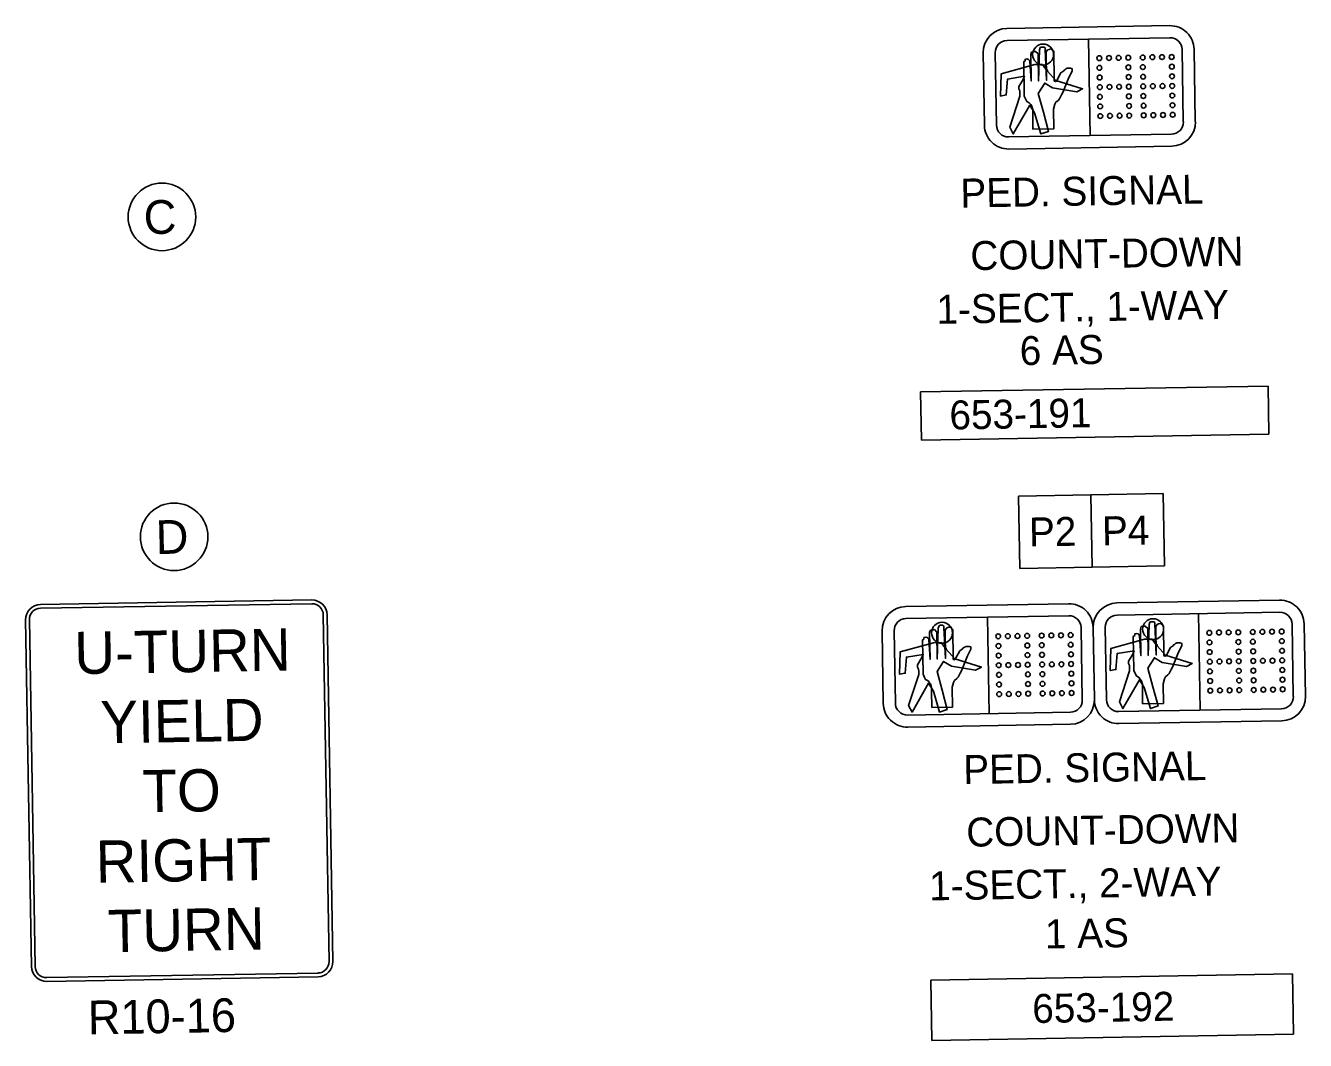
# Model space of a CAD drawing. Extents: x 924596 to 926137, y 853397 to 853834.
# Drawn here: x 925490.7 to 925596.8, y 853608.4 to 853692.5 of the extents above; entities that cross this region are included whole.
import ezdxf

# ---------------------------------------------------------------- set-up
doc = ezdxf.new("R2010")
doc.units = 0
for name, color, linetype in [('NorthArw_dp', 7, 'Continuous'), ('OverheadSign', 7, 'Continuous'), ('SignPanel', 7, 'Continuous'), ('TextNotes', 7, 'Continuous'), ('TextTables', 7, 'Continuous')]:
    doc.layers.add(name, color=color, linetype=linetype)

msp = doc.modelspace()

# ---------------------------------------------------------------- linework, layer by layer
at = {"layer": 'NorthArw_dp'}
for p, q in [((925578.79, 853691.38), (925578.92, 853683.38)), ((925564.88, 853662.12), (925593.68, 853662.61)), ((925564.95, 853658.12), (925564.88, 853662.12)), ((925593.68, 853662.61), (925593.75, 853658.61)), ((925593.75, 853658.61), (925564.95, 853658.12)), ((925572.99, 853653.48), (925578.99, 853653.59)), ((925573.09, 853647.49), (925572.99, 853653.48)), ((925578.99, 853653.59), (925584.99, 853653.69)), ((925578.99, 853653.59), (925579.09, 853647.59)), ((925579.09, 853647.59), (925578.99, 853653.59)), ((925584.99, 853653.69), (925585.09, 853647.69)), ((925579.09, 853647.59), (925573.09, 853647.49)), ((925585.09, 853647.69), (925579.09, 853647.59)), ((925587.91, 853643.74), (925588.04, 853635.74)), ((925570.41, 853643.44), (925570.55, 853635.44))]:
    msp.add_line(p, q, dxfattribs=at)
for points in [[(925572.02, 853692.26), (925585.52, 853692.49)], [(925585.54, 853691.49), (925572.04, 853691.26)], [(925570.06, 853690.23), (925570.16, 853684.23)], [(925571.06, 853690.25), (925571.16, 853684.25)], [(925586.65, 853684.51), (925586.55, 853690.51)], [(925587.65, 853684.53), (925587.55, 853690.53)], [(925572.17, 853683.26), (925585.67, 853683.49)], [(925572.19, 853682.26), (925585.69, 853682.49)], [(925581.14, 853644.62), (925594.64, 853644.85)], [(925563.64, 853644.33), (925577.14, 853644.56)], [(925577.16, 853643.56), (925563.66, 853643.33)], [(925594.66, 853643.85), (925581.16, 853643.62)], [(925578.28, 853636.57), (925578.18, 853642.57)], [(925579.18, 853642.59), (925579.28, 853636.59)], [(925580.18, 853642.61), (925580.28, 853636.61)], [(925595.77, 853636.87), (925595.67, 853642.87)], [(925596.77, 853636.89), (925596.67, 853642.89)], [(925561.68, 853642.29), (925561.78, 853636.29)], [(925562.68, 853642.31), (925562.78, 853636.31)], [(925563.8, 853635.33), (925577.29, 853635.56)], [(925581.29, 853635.62), (925594.79, 853635.85)], [(925563.81, 853634.33), (925577.31, 853634.56)], [(925581.31, 853634.62), (925594.81, 853634.85)]]:
    msp.add_lwpolyline(points, dxfattribs=at)
for points in [[(925574.19, 853683.9), (925574.17, 853685.26), (925574.17, 853685.54), (925574.08, 853685.86), (925574, 853685.94), (925573.88, 853686.09), (925573.67, 853686.21), (925573.59, 853686.37), (925573.47, 853686.65), (925573.47, 853686.73), (925573.42, 853689.49), (925573.54, 853689.57), (925573.54, 853689.69), (925573.69, 853689.73), (925573.81, 853689.69), (925573.94, 853689.57), (925573.94, 853689.53), (925574.05, 853687.9), (925574.01, 853690.1), (925574.08, 853690.3), (925574.32, 853690.34), (925574.4, 853690.34), (925574.61, 853690.15), (925574.65, 853687.91), (925574.72, 853690.47), (925574.8, 853690.67), (925574.88, 853690.71), (925575.12, 853690.71), (925575.2, 853690.64), (925575.2, 853690.52), (925575.32, 853687.96), (925575.28, 853690.32), (925575.4, 853690.48), (925575.52, 853690.52), (925575.68, 853690.56), (925575.8, 853690.49), (925575.92, 853690.37), (925575.96, 853687.97), (925575.97, 853687.89), (925576.05, 853687.85), (925576.13, 853687.89), (925576.13, 853687.89), (925576.51, 853688.58), (925576.75, 853688.74), (925576.75, 853688.78), (925576.83, 853688.82), (925576.91, 853688.91), (925577.03, 853688.95), (925577.31, 853688.95), (925577.43, 853688.91), (925577.43, 853688.83), (925577.43, 853688.79), (925577.43, 853688.75), (925577.43, 853688.71), (925577.16, 853688.19), (925576.66, 853686.94), (925576.55, 853686.74), (925576.39, 853686.42), (925576.27, 853686.29), (925576.08, 853686.13), (925576, 853685.97), (925575.89, 853685.57), (925575.91, 853683.93)], [(925574.98, 853689.27), (925574.34, 853689.26), (925571.56, 853688.49), (925571.51, 853686.65), (925571.98, 853686.74), (925572.08, 853688.06), (925573.48, 853688.29), (925573.4, 853688.09), (925573.29, 853687.88), (925573.01, 853687.44), (925573.02, 853687.24), (925573.1, 853687.08), (925573.1, 853686.88), (925573.11, 853686.68), (925573.11, 853686.64), (925572.27, 853684.07), (925572.56, 853683.51), (925573.92, 853685.89), (925574.33, 853685.26), (925574.84, 853683.51), (925575.48, 853683.72), (925575.05, 853685.31), (925574.62, 853686.87), (925575.17, 853687.72), (925575.82, 853687.33), (925577.82, 853687), (925578.3, 853687.25), (925576.09, 853687.93), (925575.39, 853688.72), (925575.39, 853688.8), (925575.27, 853688.88), (925575.27, 853688.88)], [(925565.81, 853635.96), (925565.78, 853637.32), (925565.78, 853637.6), (925565.69, 853637.92), (925565.61, 853638), (925565.49, 853638.16), (925565.29, 853638.27), (925565.2, 853638.43), (925565.08, 853638.71), (925565.08, 853638.79), (925565.03, 853641.55), (925565.15, 853641.63), (925565.15, 853641.75), (925565.31, 853641.79), (925565.43, 853641.76), (925565.55, 853641.64), (925565.55, 853641.6), (925565.66, 853639.96), (925565.62, 853642.16), (925565.7, 853642.36), (925565.94, 853642.4), (925566.02, 853642.41), (925566.22, 853642.21), (925566.26, 853639.97), (925566.33, 853642.53), (925566.41, 853642.73), (925566.49, 853642.77), (925566.73, 853642.78), (925566.81, 853642.7), (925566.81, 853642.58), (925566.94, 853640.02), (925566.9, 853642.38), (925567.01, 853642.54), (925567.13, 853642.58), (925567.29, 853642.63), (925567.41, 853642.55), (925567.54, 853642.43), (925567.58, 853640.03), (925567.58, 853639.95), (925567.66, 853639.91), (925567.74, 853639.95), (925567.74, 853639.95), (925568.13, 853640.64), (925568.36, 853640.81), (925568.36, 853640.85), (925568.44, 853640.89), (925568.52, 853640.97), (925568.64, 853641.01), (925568.92, 853641.01), (925569.04, 853640.98), (925569.04, 853640.9), (925569.04, 853640.86), (925569.04, 853640.82), (925569.04, 853640.78), (925568.77, 853640.25), (925568.27, 853639), (925568.16, 853638.8), (925568, 853638.48), (925567.89, 853638.36), (925567.69, 853638.19), (925567.61, 853638.03), (925567.5, 853637.63), (925567.53, 853635.99)], [(925583.28, 853636.26), (925583.26, 853637.62), (925583.26, 853637.9), (925583.17, 853638.22), (925583.09, 853638.3), (925582.97, 853638.45), (925582.76, 853638.57), (925582.68, 853638.73), (925582.56, 853639.01), (925582.56, 853639.09), (925582.51, 853641.85), (925582.63, 853641.93), (925582.63, 853642.05), (925582.78, 853642.09), (925582.91, 853642.05), (925583.03, 853641.93), (925583.03, 853641.89), (925583.14, 853640.26), (925583.1, 853642.46), (925583.17, 853642.66), (925583.41, 853642.7), (925583.49, 853642.7), (925583.7, 853642.51), (925583.74, 853640.27), (925583.81, 853642.83), (925583.89, 853643.03), (925583.97, 853643.07), (925584.21, 853643.07), (925584.29, 853643), (925584.29, 853642.88), (925584.41, 853640.32), (925584.37, 853642.68), (925584.49, 853642.84), (925584.61, 853642.88), (925584.77, 853642.92), (925584.89, 853642.85), (925585.01, 853642.73), (925585.05, 853640.33), (925585.06, 853640.25), (925585.14, 853640.21), (925585.22, 853640.25), (925585.22, 853640.25), (925585.6, 853640.94), (925585.84, 853641.1), (925585.84, 853641.14), (925585.92, 853641.18), (925586, 853641.27), (925586.12, 853641.31), (925586.4, 853641.31), (925586.52, 853641.27), (925586.52, 853641.19), (925586.52, 853641.15), (925586.52, 853641.11), (925586.52, 853641.07), (925586.25, 853640.55), (925585.75, 853639.3), (925585.64, 853639.1), (925585.48, 853638.78), (925585.36, 853638.65), (925585.17, 853638.49), (925585.09, 853638.33), (925584.98, 853637.93), (925585, 853636.29)], [(925584.07, 853641.63), (925583.43, 853641.62), (925580.65, 853640.85), (925580.6, 853639.01), (925581.07, 853639.1), (925581.17, 853640.42), (925582.57, 853640.65), (925582.49, 853640.45), (925582.38, 853640.24), (925582.1, 853639.8), (925582.11, 853639.6), (925582.19, 853639.44), (925582.19, 853639.24), (925582.2, 853639.04), (925582.2, 853639), (925581.36, 853636.43), (925581.65, 853635.87), (925583.01, 853638.25), (925583.42, 853637.62), (925583.93, 853635.87), (925584.57, 853636.08), (925584.14, 853637.67), (925583.71, 853639.23), (925584.26, 853640.08), (925584.91, 853639.69), (925586.91, 853639.36), (925587.39, 853639.61), (925585.18, 853640.29), (925584.48, 853641.08), (925584.48, 853641.16), (925584.36, 853641.24), (925584.36, 853641.24)], [(925566.59, 853641.34), (925565.95, 853641.32), (925563.17, 853640.56), (925563.12, 853638.72), (925563.6, 853638.8), (925563.7, 853640.13), (925565.09, 853640.35), (925565.01, 853640.15), (925564.9, 853639.95), (925564.63, 853639.5), (925564.63, 853639.3), (925564.71, 853639.14), (925564.72, 853638.94), (925564.72, 853638.74), (925564.72, 853638.7), (925563.88, 853636.13), (925564.17, 853635.57), (925565.53, 853637.96), (925565.94, 853637.32), (925566.45, 853635.57), (925567.09, 853635.78), (925566.66, 853637.38), (925566.24, 853638.93), (925566.78, 853639.78), (925567.43, 853639.39), (925569.43, 853639.06), (925569.91, 853639.31), (925567.7, 853639.99), (925567, 853640.78), (925567, 853640.86), (925566.88, 853640.94), (925566.88, 853640.94)]]:
    msp.add_lwpolyline(points, close=True, dxfattribs=at)
for centre, radius in [((925575.03, 853690.09), 0.87), ((925579.69, 853689.79), 0.2), ((925579.7, 853688.99), 0.2), ((925580.49, 853689.81), 0.2), ((925581.29, 853689.82), 0.2), ((925582.09, 853689.83), 0.2), ((925582.1, 853689.03), 0.2), ((925583.29, 853689.85), 0.2), ((925583.3, 853689.05), 0.2), ((925584.09, 853689.87), 0.2), ((925584.89, 853689.88), 0.2), ((925585.69, 853689.89), 0.2), ((925585.7, 853689.09), 0.2), ((925579.72, 853688.19), 0.2), ((925582.12, 853688.23), 0.2), ((925583.32, 853688.25), 0.2), ((925585.72, 853688.29), 0.2), ((925579.73, 853687.39), 0.2), ((925580.53, 853687.41), 0.2), ((925581.33, 853687.42), 0.2), ((925582.13, 853687.43), 0.2), ((925583.33, 853687.45), 0.2), ((925584.13, 853687.47), 0.2), ((925584.93, 853687.48), 0.2), ((925585.73, 853687.49), 0.2), ((925579.74, 853686.59), 0.2), ((925579.76, 853685.79), 0.2), ((925582.14, 853686.63), 0.2), ((925582.16, 853685.83), 0.2), ((925583.34, 853686.65), 0.2), ((925583.36, 853685.85), 0.2), ((925585.74, 853686.69), 0.2), ((925585.76, 853685.89), 0.2), ((925579.77, 853684.99), 0.2), ((925580.57, 853685.01), 0.2), ((925581.37, 853685.02), 0.2), ((925582.17, 853685.03), 0.2), ((925583.37, 853685.05), 0.2), ((925584.17, 853685.07), 0.2), ((925584.97, 853685.08), 0.2), ((925585.77, 853685.1), 0.2), ((925566.65, 853642.15), 0.87), ((925584.15, 853642.45), 0.87), ((925571.31, 853641.86), 0.2), ((925572.11, 853641.87), 0.2), ((925572.91, 853641.88), 0.2), ((925573.71, 853641.9), 0.2), ((925574.91, 853641.92), 0.2), ((925575.71, 853641.93), 0.2), ((925576.51, 853641.94), 0.2), ((925577.31, 853641.96), 0.2), ((925588.81, 853642.15), 0.2), ((925588.82, 853641.35), 0.2), ((925589.61, 853642.17), 0.2), ((925590.41, 853642.18), 0.2), ((925591.21, 853642.19), 0.2), ((925591.22, 853641.39), 0.2), ((925592.41, 853642.21), 0.2), ((925592.42, 853641.41), 0.2), ((925593.21, 853642.23), 0.2), ((925594.01, 853642.24), 0.2), ((925594.81, 853642.26), 0.2), ((925594.82, 853641.46), 0.2), ((925571.33, 853641.06), 0.2), ((925571.34, 853640.26), 0.2), ((925573.72, 853641.1), 0.2), ((925573.74, 853640.3), 0.2), ((925574.92, 853641.12), 0.2), ((925574.94, 853640.32), 0.2), ((925577.32, 853641.16), 0.2), ((925577.34, 853640.36), 0.2), ((925588.84, 853640.55), 0.2), ((925591.24, 853640.59), 0.2), ((925592.44, 853640.61), 0.2), ((925594.84, 853640.66), 0.2), ((925571.35, 853639.46), 0.2), ((925572.15, 853639.47), 0.2), ((925572.95, 853639.48), 0.2), ((925573.75, 853639.5), 0.2), ((925574.95, 853639.52), 0.2), ((925575.75, 853639.53), 0.2), ((925576.55, 853639.54), 0.2), ((925577.35, 853639.56), 0.2), ((925588.85, 853639.75), 0.2), ((925589.65, 853639.77), 0.2), ((925590.45, 853639.78), 0.2), ((925591.25, 853639.79), 0.2), ((925592.45, 853639.81), 0.2), ((925593.25, 853639.83), 0.2), ((925594.05, 853639.84), 0.2), ((925594.85, 853639.86), 0.2), ((925571.37, 853638.66), 0.2), ((925573.77, 853638.7), 0.2), ((925574.97, 853638.72), 0.2), ((925577.37, 853638.76), 0.2), ((925588.86, 853638.95), 0.2), ((925588.88, 853638.15), 0.2), ((925591.26, 853638.99), 0.2), ((925591.28, 853638.19), 0.2), ((925592.46, 853639.01), 0.2), ((925592.48, 853638.21), 0.2), ((925594.86, 853639.06), 0.2), ((925594.88, 853638.26), 0.2), ((925571.38, 853637.86), 0.2), ((925571.39, 853637.06), 0.2), ((925572.19, 853637.07), 0.2), ((925572.99, 853637.08), 0.2), ((925573.78, 853637.9), 0.2), ((925573.79, 853637.1), 0.2), ((925574.98, 853637.92), 0.2), ((925574.99, 853637.12), 0.2), ((925575.79, 853637.13), 0.2), ((925576.59, 853637.14), 0.2), ((925577.38, 853637.96), 0.2), ((925577.39, 853637.16), 0.2), ((925588.89, 853637.35), 0.2), ((925589.69, 853637.37), 0.2), ((925590.49, 853637.38), 0.2), ((925591.29, 853637.39), 0.2), ((925592.49, 853637.41), 0.2), ((925593.29, 853637.43), 0.2), ((925594.09, 853637.44), 0.2), ((925594.89, 853637.46), 0.2)]:
    msp.add_circle(centre, radius, dxfattribs=at)
for centre, radius, start, end in [((925585.55, 853690.49), 2, 0.9741, 90.9741), ((925572.06, 853690.26), 2, 90.9741, 180.9741), ((925585.55, 853690.49), 1, 0.9741, 90.9741), ((925572.06, 853690.26), 1, 90.9741, 180.9741), ((925572.16, 853684.26), 2, 180.9741, 270.9741), ((925572.16, 853684.26), 1, 180.9741, 270.9741), ((925585.66, 853684.49), 1, 270.9741, 0.9741), ((925585.66, 853684.49), 2, 270.9741, 0.9741), ((925581.18, 853642.62), 2, 90.9741, 180.9741), ((925594.67, 853642.85), 2, 0.9741, 90.9741), ((925563.68, 853642.33), 2, 90.9741, 180.9741), ((925577.18, 853642.56), 2, 0.9741, 90.9741), ((925577.18, 853642.56), 1, 0.9741, 90.9741), ((925581.18, 853642.62), 1, 90.9741, 180.9741), ((925594.67, 853642.85), 1, 0.9741, 90.9741), ((925563.68, 853642.33), 1, 90.9741, 180.9741), ((925563.78, 853636.33), 2, 180.9741, 270.9741), ((925563.78, 853636.33), 1, 180.9741, 270.9741), ((925577.28, 853636.56), 1, 270.9741, 0.9741), ((925577.28, 853636.56), 2, 270.9741, 0.9741), ((925581.28, 853636.62), 2, 180.9741, 270.9741), ((925581.28, 853636.62), 1, 180.9741, 270.9741), ((925594.78, 853636.85), 1, 270.9741, 0.9741), ((925594.78, 853636.85), 2, 270.9741, 0.9741)]:
    msp.add_arc(centre, radius, start, end, dxfattribs=at)
at = {"layer": 'OverheadSign'}
for centre in [(925501.98, 853676.63), (925502.99, 853650.11)]:
    msp.add_circle(centre, 2.8, dxfattribs=at)
at = {"layer": 'SignPanel'}
for p, q in [((925514.4, 853644.87), (925491.91, 853644.5)), ((925514.41, 853644.56), (925491.91, 853644.19)), ((925515.84, 853614.89), (925515.36, 853643.64)), ((925516.15, 853614.9), (925515.67, 853643.65)), ((925490.68, 853643.23), (925491.16, 853614.48)), ((925490.99, 853643.24), (925491.47, 853614.49)), ((925492.42, 853613.57), (925514.92, 853613.94)), ((925492.43, 853613.25), (925514.92, 853613.63))]:
    msp.add_line(p, q, dxfattribs=at)
for centre, radius, start, end in [((925514.42, 853643.62), 1.25, 0.9538, 90.9538), ((925491.93, 853643.25), 1.25, 90.9538, 180.9538), ((925491.93, 853643.25), 0.937, 90.9538, 180.9538), ((925514.42, 853643.62), 0.937, 0.9538, 90.9538), ((925514.9, 853614.88), 1.25, 270.9538, 0.9538), ((925514.9, 853614.88), 0.937, 270.9538, 0.9538), ((925492.41, 853614.5), 1.25, 180.9538, 270.9538), ((925492.41, 853614.5), 0.937, 180.9538, 270.9538)]:
    msp.add_arc(centre, radius, start, end, dxfattribs=at)
at = {"layer": 'TextNotes'}
for p, q in [((925565.71, 853613.35), (925595.71, 853613.88)), ((925595.71, 853613.88), (925595.79, 853608.88)), ((925565.8, 853608.35), (925565.71, 853613.35)), ((925595.79, 853608.88), (925565.8, 853608.35))]:
    msp.add_line(p, q, dxfattribs=at)

# ---------------------------------------------------------------- texts
at = {"layer": 'NorthArw_dp'}
for s, rotation, p in [('PED. SIGNAL', 0.9741, (925568.19, 853677.4)), ('COUNT-DOWN', 0.9741, (925569.02, 853672.21)), ('1-SECT., 1-WAY', 0.9741, (925566.21, 853667.76)), (' 6 AS ', 0.9741, (925572.22, 853664.32)), ('  653-191   ', 0.9741, (925565.5, 853658.97)), ('P2', 0.9946, (925573.88, 853649.3)), ('P4', 0.9946, (925579.93, 853649.4)), ('PED. SIGNAL', 0.9741, (925568.43, 853629.6)), ('COUNT-DOWN', 0.9741, (925568.68, 853624.41)), ('1-SECT., 2-WAY', 0.9741, (925565.6, 853619.96)), (' 1 AS ', 0.9741, (925574.31, 853615.96))]:
    msp.add_text(s, height=2.4, rotation=rotation, dxfattribs=at).set_placement(p)
at = {"layer": 'OverheadSign'}
for s, rotation, p in [('C', 1.3325, (925500.5, 853675.19)), ('D', 1.3122, (925501.5, 853648.67))]:
    msp.add_text(s, height=2.8, rotation=rotation, dxfattribs=at).set_placement(p)
at = {"layer": 'SignPanel'}
for s, p in [('U-TURN', (925494.74, 853638.72)), ('YIELD', (925496.91, 853632.98)), ('TO', (925500.39, 853627.26)), ('RIGHT', (925496.52, 853621.42)), ('TURN', (925497.52, 853615.67))]:
    msp.add_text(s, height=3.5, rotation=0.9538, dxfattribs=at).set_placement(p)
at = {"layer": 'TextNotes'}
msp.add_text('653-192', height=2.4, rotation=1.0027, dxfattribs=at).set_placement((925574.15, 853609.79))
at = {"layer": 'TextTables'}
msp.add_text('R10-16', height=2.8, rotation=0.9741, dxfattribs=at).set_placement((925495.86, 853608.85))

doc.saveas('drawing.dxf')
